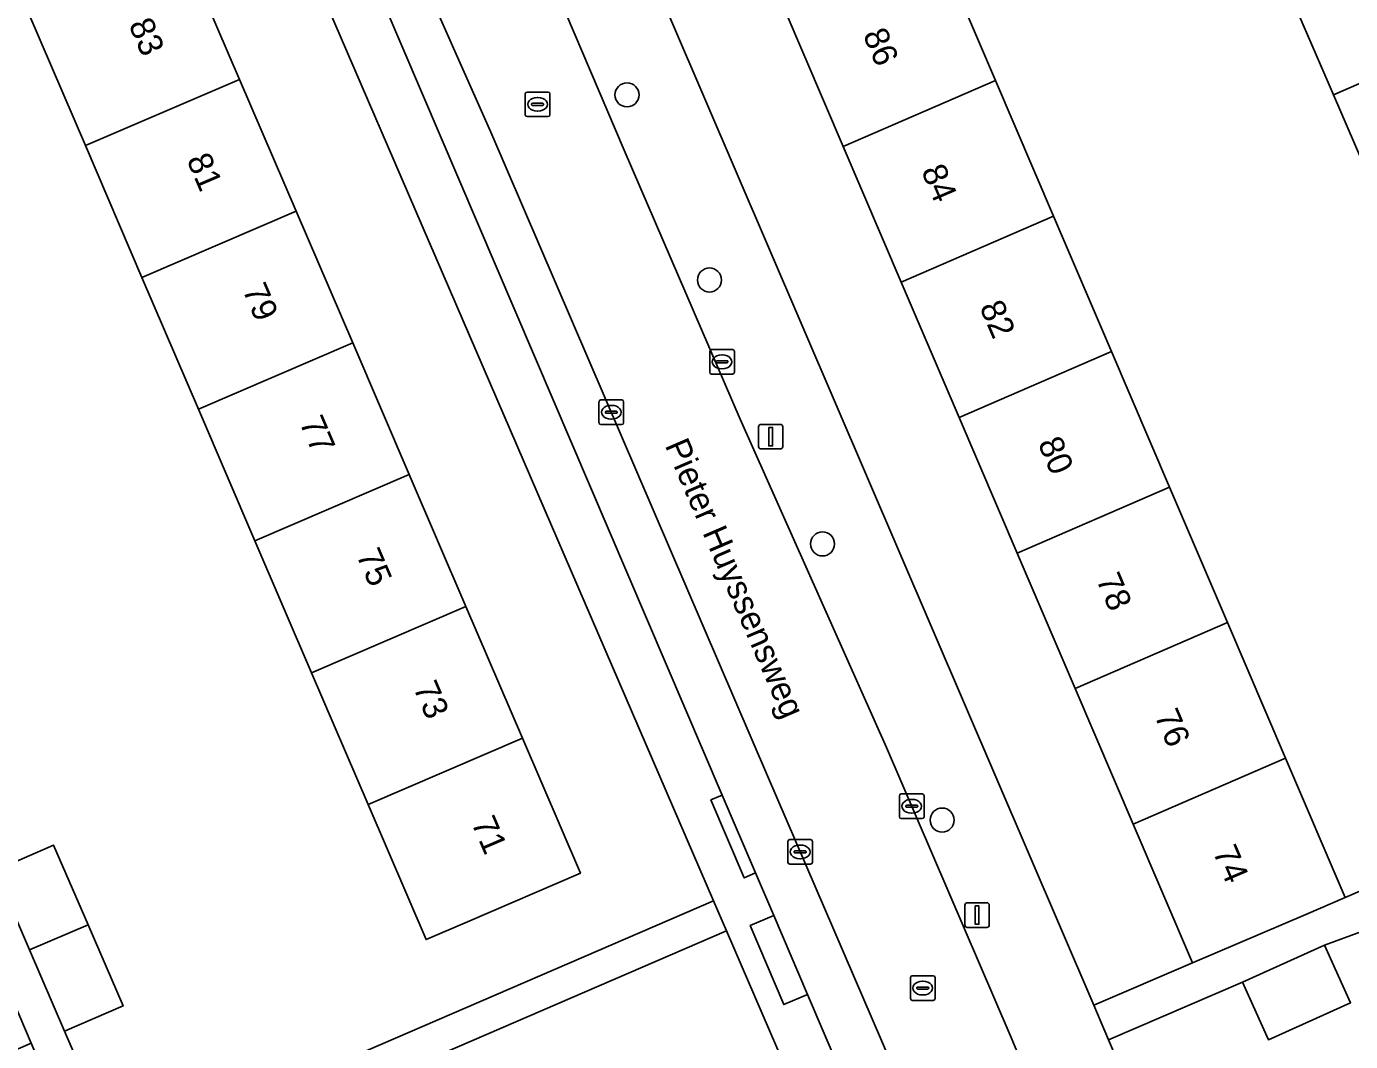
# Model space of a CAD drawing. Extents: x 159352 to 160617, y 385888 to 387323.
# Drawn here: x 159634.4 to 159688.2, y 386352.7 to 386393.9 of the extents above; entities that cross this region are included whole.
import ezdxf

# ---------------------------------------------------------------- set-up
doc = ezdxf.new("R2010")
doc.units = 0
for name, color, linetype in [('IMGEO_Boom', 7, 'Continuous'), ('IMGEO_Erf', 7, 'Continuous'), ('IMGEO_Kolk', 7, 'Continuous'), ('IMGEO_Lichtmast', 7, 'Continuous'), ('IMGEO_Openbare_ruimte_label', 7, 'Continuous'), ('IMGEO_Pand', 7, 'Continuous'), ('IMGEO_Pand_nummerreeks', 7, 'Continuous'), ('IMGEO_Parkeervlak_open', 7, 'Continuous'), ('IMGEO_Rijbaan_lokaal_open', 7, 'Continuous'), ('IMGEO_Rioolput', 7, 'Continuous'), ('IMGEO_Voetpad_open', 7, 'Continuous')]:
    doc.layers.add(name, color=color, linetype=linetype)

msp = doc.modelspace()

# ---------------------------------------------------------------- linework, layer by layer
at = {"layer": 'IMGEO_Boom'}
for centre in [(159658.804, 386391.157), (159662.157, 386383.63), (159666.757, 386372.899), (159671.622, 386361.672)]:
    msp.add_circle(centre, 0.489, dxfattribs=at)
at = {"layer": 'IMGEO_Erf'}
msp.add_lwpolyline([(159669.952, 386383.548), (159667.592, 386389.058), (159665.231, 386394.568), (159662.871, 386400.077), (159660.51, 386405.587), (159658.09, 386411.236), (159654.031, 386409.485), (159677.79, 386354.14), (159681.812, 386355.866), (159679.394, 386361.509), (159677.034, 386367.019), (159674.673, 386372.53), (159672.312, 386378.04)], close=True, dxfattribs=at)
for points in [[(159618.339, 386393.996), (159619.3, 386391.771), (159621.681, 386392.8), (159623.081, 386389.56), (159624.506, 386386.261), (159622.125, 386385.232), (159623.9, 386381.056), (159626.281, 386382.085), (159627.681, 386378.844), (159629.106, 386375.546), (159626.725, 386374.517), (159628.5, 386370.342), (159630.881, 386371.371), (159632.282, 386368.129), (159633.706, 386364.832), (159631.325, 386363.803), (159633.1, 386359.628), (159635.481, 386360.657), (159636.881, 386357.416), (159638.306, 386354.118), (159635.925, 386353.089), (159638.142, 386347.957), (159662.319, 386358.392), (159642.474, 386404.373)], [(159671.433, 386397.252), (159673.793, 386391.741), (159676.152, 386386.232), (159678.511, 386380.722), (159680.871, 386375.212), (159683.231, 386369.701), (159685.59, 386364.191), (159688.018, 386358.522), (159701.797, 386364.467)], [(159640.743, 386397.144), (159643.044, 386391.788), (159645.345, 386386.431), (159647.646, 386381.074), (159649.946, 386375.718), (159652.247, 386370.361), (159654.548, 386365.004), (159656.908, 386359.509), (159652.314, 386357.536), (159650.63, 386356.812), (159648.271, 386362.308), (159645.971, 386367.665), (159643.671, 386373.022), (159641.371, 386378.38), (159639.071, 386383.736), (159636.771, 386389.094), (159634.471, 386394.451)], [(159688.945, 386387.891), (159687.535, 386391.16), (159686.131, 386394.413)], [(159727.536, 386373.743), (159720.249, 386370.605), (159721.28, 386368.219), (159718.093, 386366.842), (159714.716, 386365.384), (159713.685, 386367.77), (159709.209, 386365.826), (159710.24, 386363.44), (159707.052, 386362.063), (159703.676, 386360.605), (159702.645, 386362.991), (159698.168, 386361.048), (159699.199, 386358.662), (159696.011, 386357.285), (159692.635, 386355.827), (159691.604, 386358.213), (159687.18, 386356.583), (159688.233, 386354.242), (159684.894, 386352.739), (159683.84, 386355.08), (159678.391, 386352.741), (159688.233, 386329.814)], [(159684.092, 386307.943), (159677.65, 386322.87), (159662.847, 386357.169), (159638.742, 386346.766), (159641.054, 386341.414), (159643.435, 386342.443), (159644.854, 386339.16), (159646.26, 386335.904), (159643.879, 386334.875), (159645.691, 386330.715), (159648.072, 386331.744), (159649.491, 386328.459), (159650.897, 386325.205), (159648.516, 386324.176), (159650.328, 386320.017), (159652.709, 386321.046), (159654.128, 386317.763)]]:
    msp.add_lwpolyline(points, dxfattribs=at)
at = {"layer": 'IMGEO_Kolk'}
for p, q in [((159662.169, 386379.877), (159662.169, 386380.729)), ((159662.244, 386380.803), (159663.096, 386380.803)), ((159662.657, 386380.583), (159662.682, 386380.583)), ((159663.17, 386380.729), (159663.17, 386379.877)), ((159662.428, 386380.297), (159662.428, 386380.309)), ((159662.866, 386380.26), (159662.468, 386380.26)), ((159662.471, 386380.346), (159662.869, 386380.346)), ((159662.68, 386380.023), (159662.655, 386380.023)), ((159662.912, 386380.309), (159662.912, 386380.297)), ((159663.096, 386379.803), (159662.244, 386379.803)), ((159657.664, 386377.827), (159657.664, 386378.679)), ((159657.739, 386378.753), (159658.591, 386378.753)), ((159658.152, 386378.533), (159658.177, 386378.533)), ((159658.665, 386378.679), (159658.665, 386377.827)), ((159657.923, 386378.247), (159657.923, 386378.259)), ((159658.361, 386378.21), (159657.963, 386378.21)), ((159657.966, 386378.296), (159658.364, 386378.296)), ((159658.175, 386377.973), (159658.15, 386377.973)), ((159658.407, 386378.259), (159658.407, 386378.247)), ((159658.591, 386377.753), (159657.739, 386377.753)), ((159669.884, 386361.808), (159669.884, 386362.66)), ((159669.959, 386362.734), (159670.811, 386362.734)), ((159670.143, 386362.228), (159670.143, 386362.24)), ((159670.186, 386362.277), (159670.584, 386362.277)), ((159670.372, 386362.514), (159670.397, 386362.514)), ((159670.627, 386362.24), (159670.627, 386362.228)), ((159670.885, 386362.66), (159670.885, 386361.808)), ((159670.811, 386361.734), (159669.959, 386361.734)), ((159670.581, 386362.191), (159670.183, 386362.191)), ((159670.395, 386361.954), (159670.37, 386361.954)), ((159665.346, 386359.952), (159665.346, 386360.804)), ((159665.421, 386360.878), (159666.273, 386360.878)), ((159665.834, 386360.658), (159665.859, 386360.658)), ((159666.347, 386360.804), (159666.347, 386359.952)), ((159665.605, 386360.372), (159665.605, 386360.384)), ((159666.043, 386360.335), (159665.645, 386360.335)), ((159665.648, 386360.421), (159666.046, 386360.421)), ((159665.857, 386360.098), (159665.832, 386360.098)), ((159666.089, 386360.384), (159666.089, 386360.372)), ((159666.273, 386359.878), (159665.421, 386359.878))]:
    msp.add_line(p, q, dxfattribs=at)
for points in [[(159662.169, 386379.877), (159662.169, 386380.729)], [(159662.244, 386380.803), (159663.096, 386380.803)], [(159663.17, 386380.729), (159663.17, 386379.877)], [(159663.096, 386379.803), (159662.244, 386379.803)], [(159657.664, 386377.827), (159657.664, 386378.679)], [(159657.739, 386378.753), (159658.591, 386378.753)], [(159658.665, 386378.679), (159658.665, 386377.827)], [(159658.591, 386377.753), (159657.739, 386377.753)], [(159669.884, 386361.808), (159669.884, 386362.66)], [(159669.959, 386362.734), (159670.811, 386362.734)], [(159670.885, 386362.66), (159670.885, 386361.808)], [(159670.811, 386361.734), (159669.959, 386361.734)], [(159665.346, 386359.952), (159665.346, 386360.804)], [(159665.421, 386360.878), (159666.273, 386360.878)], [(159666.347, 386360.804), (159666.347, 386359.952)], [(159666.273, 386359.878), (159665.421, 386359.878)]]:
    msp.add_lwpolyline(points, dxfattribs=at)
for centre, radius, start, end in [((159662.246, 386380.727), 0.0765, 91.552, 178.448), ((159662.246, 386380.727), 0.0765, 91.552, 178.448), ((159663.094, 386380.727), 0.0765, 1.552, 88.448), ((159663.094, 386380.727), 0.0765, 1.552, 88.448), ((159662.468, 386380.306), 0.0403, 85.8775, 175.7526), ((159662.465, 386380.296), 0.0366, 178.938, 274.7102), ((159662.869, 386380.303), 0.043, 264.8664, 352.4533), ((159662.873, 386380.308), 0.0386, 1.7309, 96.639), ((159662.246, 386379.879), 0.0765, 181.552, 268.448), ((159662.246, 386379.879), 0.0765, 181.552, 268.448), ((159663.094, 386379.879), 0.0765, 271.552, 358.448), ((159663.094, 386379.879), 0.0765, 271.552, 358.448), ((159657.741, 386378.677), 0.0765, 91.552, 178.448), ((159657.741, 386378.677), 0.0765, 91.552, 178.448), ((159658.589, 386378.677), 0.0765, 1.552, 88.448), ((159658.589, 386378.677), 0.0765, 1.552, 88.448), ((159657.963, 386378.256), 0.0403, 85.8775, 175.7526), ((159657.96, 386378.246), 0.0366, 178.938, 274.7102), ((159658.364, 386378.253), 0.043, 264.8664, 352.4533), ((159658.368, 386378.258), 0.0386, 1.7309, 96.639), ((159657.741, 386377.829), 0.0765, 181.552, 268.448), ((159657.741, 386377.829), 0.0765, 181.552, 268.448), ((159658.589, 386377.829), 0.0765, 271.552, 358.448), ((159658.589, 386377.829), 0.0765, 271.552, 358.448), ((159669.961, 386362.658), 0.0765, 91.552, 178.448), ((159669.961, 386362.658), 0.0765, 91.552, 178.448), ((159670.183, 386362.237), 0.0403, 85.8775, 175.7526), ((159670.18, 386362.227), 0.0366, 178.938, 274.7102), ((159670.584, 386362.234), 0.043, 264.8664, 352.4533), ((159670.588, 386362.239), 0.0386, 1.7309, 96.639), ((159670.809, 386362.658), 0.0765, 1.552, 88.448), ((159670.809, 386362.658), 0.0765, 1.552, 88.448), ((159669.961, 386361.81), 0.0765, 181.552, 268.448), ((159669.961, 386361.81), 0.0765, 181.552, 268.448), ((159670.809, 386361.81), 0.0765, 271.552, 358.448), ((159670.809, 386361.81), 0.0765, 271.552, 358.448), ((159665.423, 386360.802), 0.0765, 91.552, 178.448), ((159665.423, 386360.802), 0.0765, 91.552, 178.448), ((159666.271, 386360.802), 0.0765, 1.552, 88.448), ((159666.271, 386360.802), 0.0765, 1.552, 88.448), ((159665.645, 386360.381), 0.0403, 85.8775, 175.7526), ((159665.642, 386360.371), 0.0366, 178.938, 274.7102), ((159666.046, 386360.378), 0.043, 264.8664, 352.4533), ((159666.05, 386360.383), 0.0386, 1.7309, 96.639), ((159665.423, 386359.954), 0.0765, 181.552, 268.448), ((159665.423, 386359.954), 0.0765, 181.552, 268.448), ((159666.271, 386359.954), 0.0765, 271.552, 358.448), ((159666.271, 386359.954), 0.0765, 271.552, 358.448)]:
    msp.add_arc(centre, radius, start, end, dxfattribs=at)
for centre, major_axis, ratio, start_param, end_param in [((159662.656, 386380.303), (-0.387, 0.002), 0.722429, 4.712389, 7.853982), ((159662.681, 386380.303), (-0.39, 0.002), 0.717154, 1.570796, 4.712389), ((159658.151, 386378.253), (-0.387, 0.002), 0.722429, 4.712389, 7.853982), ((159658.176, 386378.253), (-0.39, 0.002), 0.717154, 1.570796, 4.712389), ((159670.371, 386362.234), (-0.387, 0.002), 0.722429, 4.712389, 7.853982), ((159670.396, 386362.234), (-0.39, 0.002), 0.717154, 1.570796, 4.712389), ((159665.833, 386360.378), (-0.387, 0.002), 0.722429, 4.712389, 7.853982), ((159665.858, 386360.378), (-0.39, 0.002), 0.717154, 1.570796, 4.712389)]:
    msp.add_ellipse(centre, major_axis=major_axis, ratio=ratio, start_param=start_param, end_param=end_param, dxfattribs=at)
at = {"layer": 'IMGEO_Lichtmast'}
for p, q in [((159664.152, 386376.861), (159664.152, 386377.661)), ((159664.152, 386377.661), (159664.152, 386376.861)), ((159664.252, 386377.761), (159665.042, 386377.761)), ((159665.042, 386377.761), (159664.252, 386377.761)), ((159665.142, 386377.661), (159665.142, 386376.861)), ((159665.142, 386376.861), (159665.142, 386377.661)), ((159665.042, 386376.761), (159664.252, 386376.761)), ((159664.252, 386376.761), (159665.042, 386376.761)), ((159672.546, 386357.408), (159672.546, 386358.208)), ((159672.546, 386358.208), (159672.546, 386357.408)), ((159672.646, 386358.308), (159673.436, 386358.308)), ((159673.436, 386358.308), (159672.646, 386358.308)), ((159673.536, 386358.208), (159673.536, 386357.408)), ((159673.536, 386357.408), (159673.536, 386358.208)), ((159673.436, 386357.308), (159672.646, 386357.308)), ((159672.646, 386357.308), (159673.436, 386357.308))]:
    msp.add_line(p, q, dxfattribs=at)
for points in [[(159664.572, 386377.636), (159664.722, 386377.636), (159664.722, 386376.886), (159664.572, 386376.886), (159664.572, 386377.636)], [(159672.966, 386358.183), (159673.116, 386358.183), (159673.116, 386357.433), (159672.966, 386357.433), (159672.966, 386358.183)]]:
    msp.add_lwpolyline(points, dxfattribs=at)
for centre, start, end in [((159664.252, 386377.661), 90, 180), ((159664.252, 386377.661), 90, 180), ((159665.042, 386377.661), 0, 90), ((159665.042, 386377.661), 360, 90), ((159664.252, 386376.861), 180, 270), ((159664.252, 386376.861), 180, 270), ((159665.042, 386376.861), 270, 0), ((159665.042, 386376.861), 270, 0), ((159672.646, 386358.208), 90, 180), ((159672.646, 386358.208), 90, 180), ((159673.436, 386358.208), 0, 90), ((159673.436, 386358.208), 360, 90), ((159672.646, 386357.408), 180, 270), ((159672.646, 386357.408), 180, 270), ((159673.436, 386357.408), 270, 0), ((159673.436, 386357.408), 270, 0)]:
    msp.add_arc(centre, 0.1, start, end, dxfattribs=at)
at = {"layer": 'IMGEO_Pand'}
for points in [[(159673.793, 386391.741), (159671.433, 386397.252), (159665.231, 386394.568), (159667.592, 386389.058)], [(159634.471, 386394.451), (159636.771, 386389.094), (159643.044, 386391.788), (159640.743, 386397.144)], [(159688.506, 386395.437), (159686.131, 386394.413), (159687.535, 386391.16), (159689.908, 386392.187)], [(159688.945, 386387.891), (159691.32, 386388.915), (159689.908, 386392.187), (159687.535, 386391.16)], [(159645.345, 386386.431), (159643.044, 386391.788), (159636.771, 386389.094), (159639.071, 386383.736)], [(159676.152, 386386.232), (159673.793, 386391.741), (159667.592, 386389.058), (159669.952, 386383.548)], [(159639.071, 386383.736), (159641.371, 386378.38), (159647.646, 386381.074), (159645.345, 386386.431)], [(159669.952, 386383.548), (159672.312, 386378.04), (159678.511, 386380.722), (159676.152, 386386.232)], [(159649.946, 386375.718), (159647.646, 386381.074), (159641.371, 386378.38), (159643.671, 386373.022)], [(159672.312, 386378.04), (159674.673, 386372.53), (159680.871, 386375.212), (159678.511, 386380.722)], [(159643.671, 386373.022), (159645.971, 386367.665), (159652.247, 386370.361), (159649.946, 386375.718)], [(159683.231, 386369.701), (159680.871, 386375.212), (159674.673, 386372.53), (159677.034, 386367.019)], [(159645.971, 386367.665), (159648.271, 386362.308), (159654.548, 386365.004), (159652.247, 386370.361)], [(159685.59, 386364.191), (159683.231, 386369.701), (159677.034, 386367.019), (159679.394, 386361.509)], [(159648.271, 386362.308), (159650.63, 386356.812), (159652.314, 386357.536), (159656.908, 386359.509), (159654.548, 386365.004)], [(159679.394, 386361.509), (159681.812, 386355.866), (159686.409, 386357.833), (159688.018, 386358.522), (159685.59, 386364.191)], [(159635.481, 386360.657), (159633.1, 386359.628), (159634.498, 386356.392), (159636.881, 386357.416)], [(159635.925, 386353.089), (159638.306, 386354.118), (159636.881, 386357.416), (159634.498, 386356.392)], [(159688.233, 386354.242), (159687.18, 386356.583), (159683.84, 386355.08), (159684.894, 386352.739)], [(159632.191, 386351.569), (159634.573, 386352.598), (159633.165, 386355.857), (159630.781, 386354.833)]]:
    msp.add_lwpolyline(points, close=True, dxfattribs=at)
at = {"layer": 'IMGEO_Parkeervlak_open'}
for points in [[(159653.271, 386389.647), (159647, 386403.746)], [(159646.602, 386400.263), (159662.676, 386362.691), (159664.032, 386359.521), (159664.771, 386357.792), (159666.145, 386354.581), (159678.232, 386326.328)], [(159679.143, 386325.423), (159680.512, 386324.81), (159681.53, 386324.098), (159679.223, 386329.328), (159664.516, 386363.471), (159653.271, 386389.647)]]:
    msp.add_lwpolyline(points, dxfattribs=at)
at = {"layer": 'IMGEO_Rijbaan_lokaal_open'}
for points in [[(159685.711, 386326.516), (159680.586, 386338.124), (159674.395, 386352.921), (159669.357, 386364.619), (159663.41, 386377.978), (159658.694, 386388.914), (159646.44, 386417.646)], [(159641.964, 386415.245), (159647, 386403.746), (159653.271, 386389.647), (159664.516, 386363.471), (159679.223, 386329.328), (159681.53, 386324.098), (159682.399, 386322.126)]]:
    msp.add_lwpolyline(points, dxfattribs=at)
at = {"layer": 'IMGEO_Rioolput'}
for p, q in [((159654.666, 386390.347), (159654.666, 386391.199)), ((159654.741, 386391.273), (159655.593, 386391.273)), ((159654.925, 386390.767), (159654.925, 386390.779)), ((159654.968, 386390.816), (159655.366, 386390.816)), ((159655.154, 386391.053), (159655.179, 386391.053)), ((159655.409, 386390.779), (159655.409, 386390.767)), ((159655.667, 386391.199), (159655.667, 386390.347)), ((159655.593, 386390.273), (159654.741, 386390.273)), ((159655.363, 386390.73), (159654.965, 386390.73)), ((159655.177, 386390.493), (159655.152, 386390.493)), ((159670.333, 386354.415), (159670.333, 386355.267)), ((159670.408, 386355.341), (159671.26, 386355.341)), ((159671.334, 386355.267), (159671.334, 386354.415)), ((159670.592, 386354.835), (159670.592, 386354.847)), ((159671.03, 386354.798), (159670.632, 386354.798)), ((159670.635, 386354.884), (159671.033, 386354.884)), ((159670.821, 386355.121), (159670.846, 386355.121)), ((159671.076, 386354.847), (159671.076, 386354.835)), ((159671.26, 386354.341), (159670.408, 386354.341)), ((159670.844, 386354.561), (159670.819, 386354.561))]:
    msp.add_line(p, q, dxfattribs=at)
for points in [[(159654.666, 386390.347), (159654.666, 386391.199)], [(159654.741, 386391.273), (159655.593, 386391.273)], [(159655.667, 386391.199), (159655.667, 386390.347)], [(159655.593, 386390.273), (159654.741, 386390.273)], [(159670.333, 386354.415), (159670.333, 386355.267)], [(159670.408, 386355.341), (159671.26, 386355.341)], [(159671.334, 386355.267), (159671.334, 386354.415)], [(159671.26, 386354.341), (159670.408, 386354.341)]]:
    msp.add_lwpolyline(points, dxfattribs=at)
for centre, radius, start, end in [((159654.743, 386391.197), 0.0765, 91.552, 178.448), ((159654.743, 386391.197), 0.0765, 91.552, 178.448), ((159654.965, 386390.776), 0.0403, 85.8775, 175.7526), ((159654.962, 386390.766), 0.0366, 178.938, 274.7102), ((159655.366, 386390.773), 0.043, 264.8664, 352.4533), ((159655.37, 386390.778), 0.0386, 1.7309, 96.639), ((159655.591, 386391.197), 0.0765, 1.552, 88.448), ((159655.591, 386391.197), 0.0765, 1.552, 88.448), ((159654.743, 386390.349), 0.0765, 181.552, 268.448), ((159654.743, 386390.349), 0.0765, 181.552, 268.448), ((159655.591, 386390.349), 0.0765, 271.552, 358.448), ((159655.591, 386390.349), 0.0765, 271.552, 358.448), ((159670.41, 386355.265), 0.0765, 91.552, 178.448), ((159670.41, 386355.265), 0.0765, 91.552, 178.448), ((159671.258, 386355.265), 0.0765, 1.552, 88.448), ((159671.258, 386355.265), 0.0765, 1.552, 88.448), ((159670.632, 386354.844), 0.0403, 85.8775, 175.7526), ((159670.629, 386354.834), 0.0366, 178.938, 274.7102), ((159671.033, 386354.841), 0.043, 264.8664, 352.4533), ((159671.037, 386354.846), 0.0386, 1.7309, 96.639), ((159670.41, 386354.417), 0.0765, 181.552, 268.448), ((159670.41, 386354.417), 0.0765, 181.552, 268.448), ((159671.258, 386354.417), 0.0765, 271.552, 358.448), ((159671.258, 386354.417), 0.0765, 271.552, 358.448)]:
    msp.add_arc(centre, radius, start, end, dxfattribs=at)
for centre, major_axis, ratio, start_param, end_param in [((159655.153, 386390.773), (-0.387, 0.002), 0.722429, 4.712389, 7.853982), ((159655.178, 386390.773), (-0.39, 0.002), 0.717154, 1.570796, 4.712389), ((159670.82, 386354.841), (-0.387, 0.002), 0.722429, 4.712389, 7.853982), ((159670.845, 386354.841), (-0.39, 0.002), 0.717154, 1.570796, 4.712389)]:
    msp.add_ellipse(centre, major_axis=major_axis, ratio=ratio, start_param=start_param, end_param=end_param, dxfattribs=at)
at = {"layer": 'IMGEO_Voetpad_open'}
for points in [[(159646.44, 386417.646), (159658.694, 386388.914), (159663.41, 386377.978), (159669.357, 386364.619), (159674.395, 386352.921), (159680.586, 386338.124), (159685.711, 386326.516)], [(159637.775, 386414.365), (159639.951, 386409.655), (159640.145, 386409.246), (159642.474, 386404.373), (159662.319, 386358.392), (159662.847, 386357.169), (159677.65, 386322.87), (159681.53, 386324.098), (159680.512, 386324.81), (159679.143, 386325.423)], [(159688.233, 386329.814), (159678.391, 386352.741), (159677.79, 386354.14), (159654.031, 386409.485)], [(159678.232, 386326.328), (159666.145, 386354.581), (159665.189, 386354.172), (159663.815, 386357.383), (159664.771, 386357.792), (159664.032, 386359.521), (159663.573, 386359.323), (159662.217, 386362.493), (159662.676, 386362.691), (159646.602, 386400.263)], [(159701.797, 386364.467), (159688.018, 386358.522), (159686.409, 386357.833), (159681.812, 386355.866), (159677.79, 386354.14), (159678.391, 386352.741), (159683.84, 386355.08), (159687.18, 386356.583), (159691.604, 386358.213)], [(159651.748, 386316.73), (159650.328, 386320.017), (159648.516, 386324.176), (159647.112, 386327.426), (159645.691, 386330.715), (159643.879, 386334.875), (159642.474, 386338.127), (159641.054, 386341.414), (159638.742, 386346.766), (159662.847, 386357.169), (159662.319, 386358.392), (159638.142, 386347.957), (159635.925, 386353.089), (159634.498, 386356.392), (159633.1, 386359.628)], [(159633.165, 386355.857), (159634.573, 386352.598), (159636.817, 386347.385), (159624.606, 386342.094)]]:
    msp.add_lwpolyline(points, dxfattribs=at)
for points in [[(159664.032, 386359.521), (159662.676, 386362.691), (159662.217, 386362.493), (159663.573, 386359.323)], [(159664.771, 386357.792), (159663.815, 386357.383), (159665.189, 386354.172), (159666.145, 386354.581)]]:
    msp.add_lwpolyline(points, close=True, dxfattribs=at)

# ---------------------------------------------------------------- texts
at = {"layer": 'IMGEO_Openbare_ruimte_label'}
msp.add_text('Pieter Huyssensweg', height=1, rotation=293.334, dxfattribs=at).set_placement((159660.33, 386376.912))
at = {"layer": 'IMGEO_Pand_nummerreeks'}
for s, rotation, p in [('83', 293.2438, (159638.517, 386394.018)), ('86', 293.1916, (159668.383, 386393.609)), ('81', 293.2438, (159640.877, 386388.523)), ('84', 293.1916, (159670.756, 386388.072)), ('79', 293.2438, (159643.148, 386383.236)), ('82', 293.1916, (159673.127, 386382.538)), ('77', 293.2438, (159645.464, 386377.844)), ('80', 293.1916, (159675.501, 386376.995)), ('75', 293.2438, (159647.779, 386372.453)), ('78', 293.1916, (159677.873, 386371.458)), ('73', 293.2438, (159650.095, 386367.062)), ('76', 293.1916, (159680.244, 386365.924)), ('71', 293.2438, (159652.456, 386361.566)), ('74', 293.1916, (159682.617, 386360.387))]:
    msp.add_text(s, height=1, rotation=rotation, dxfattribs=at).set_placement(p)

doc.saveas('drawing.dxf')
